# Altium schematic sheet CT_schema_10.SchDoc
size 147 x 119 mm
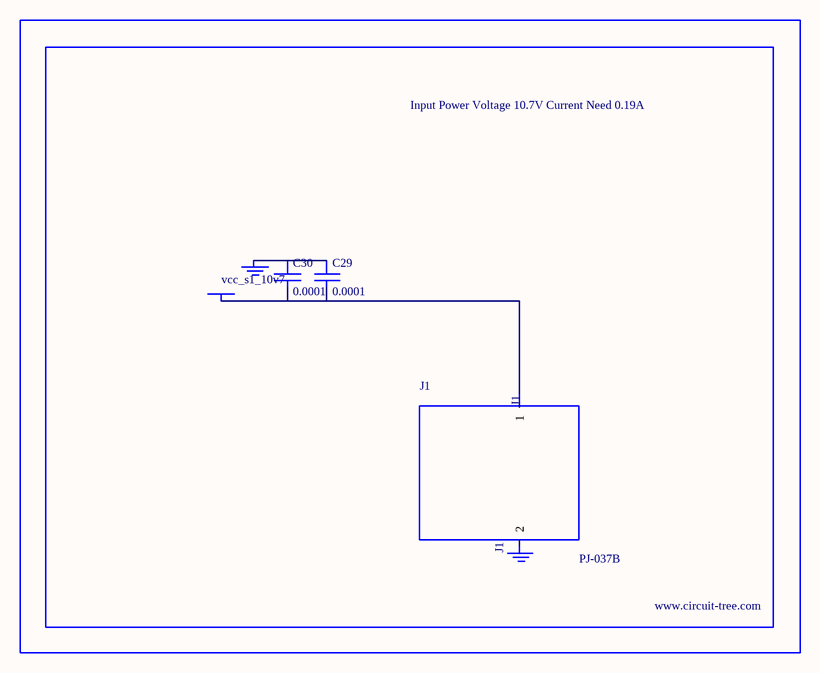
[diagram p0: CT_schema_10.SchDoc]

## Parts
BORDER9  (no value)
C29  0.0001  [EXV-9H]
C30  0.0001  [EXV-9H]
GND_INSTANCE_9_0  (no value)
GND_INSTANCE_9_1  (no value)
J1  PJ-037B  [PJ-037B_PACKAGE]
POWER_INSTANCE_9_0  vcc_s1_10v7

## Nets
NetC29_1: C29.1 C30.1 GND_INSTANCE_9_0.0(GND)
NetC29_2: C29.2 C30.2 J1.1 POWER_INSTANCE_9_0.0(PWR)

Not connected (* = marked no-connect by the designer): GND_INSTANCE_9_1 0(GND); J1 2

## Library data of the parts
BORDER9 = BORDER_PAGE9
C29 C30 = EDK107M035A9HAA
GND_INSTANCE_9_0 GND_INSTANCE_9_1 = GND
POWER_INSTANCE_9_0 = PWR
